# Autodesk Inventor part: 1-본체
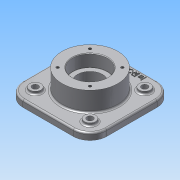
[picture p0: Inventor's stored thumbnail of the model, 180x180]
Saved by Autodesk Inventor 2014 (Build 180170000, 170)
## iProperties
Created: 2015-09
Part Number: 1-본체
Material: 알루미늄 6061
Document SubType Name: Modeling
Designer: study
Density: 2.71 g/cm^3
Appearance: 알루미늄 - 평지
Mass: 1464.68 g
Surface Area: 800.934 cm^2
Volume: 540.471 cm^3
Author: study
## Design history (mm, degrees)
sketch "스케치1"
  geometry: L1 (75, -75)-(-75, -75); L2 (-75, -75)-(-75, 75); L3 (-75, 75)-(75, 75); L4 (75, 75)-(75, -75); 3 further points
  constraints: 8 end point, 1 coincident, 1 midpoint, 1 vertical alignment, 9 other
  dimensions: "d0" = 150 distance of L2.end L3.end
extrude "돌출1" new body sketch "스케치1" distance "d1" = 12; taper "d2" = 0 deg
fillet "모깎기1" dims "d3" = 30
sketch "스케치2"
  geometry: C1 r 50 at (0, 0); 1 further point
  constraints: 1 centre point, 1 coincident
  dimensions: "d4" = 100 diameter of C1
extrude "돌출2" join sketch "스케치2" distance "d5" = 23; taper "d6" = 0 deg
node "작업 평면1"
sketch "스케치3"
  geometry: C1 r 50 at (0, 0); 1 further point
  constraints: 1 centre point, 1 coincident
  dimensions: "d8" = 100 diameter of C1
extrude "돌출3" join sketch "스케치3" stored distance "d9" = 23; taper "d10" = 0 deg
hole "구멍1" diameter "d13" = 45; stored, may be unused: countersink angle "d17" = 90 deg, drill point angle "d19" = 0 deg; dims "d11" = 10, "d12" = 10, "d14" = 6, "d15" = 62, "d16" = 22, "d18" = 8
hole "구멍2" diameter "d22" = 45; stored, may be unused: countersink angle "d26" = 90 deg, drill point angle "d28" = 0 deg; dims "d20" = 10, "d21" = 10, "d23" = 6, "d24" = 62, "d25" = 22, "d27" = 8
node "작업 평면2"
sketch "스케치5"
  geometry: L1 (49, -49)-(-49, -49); L2 (-49, -49)-(-49, 49); L3 (-49, 49)-(49, 49); L4 (49, 49)-(49, -49); C1 r 10 at (-49, 49); C2 r 10 at (49, 49); C3 r 10 at (49, -49); C4 r 10 at (-49, -49); 3 further points
  constraints: 8 end point, 5 coincident, 4 centre point, 3 equal radius, 1 midpoint, 1 vertical alignment, 9 other
  dimensions: "d31" = 98 distance of L2.end L3.end; "d32" = 20 diameter of C1
extrude "돌출4" join sketch "스케치5" stored distance "d33" = 23; taper "d34" = 0 deg
sketch "스케치6"
  geometry: C1 r 10 at (0, 0) reference; C2 r 10 at (0, 98) reference; C3 r 10 at (-98, 98) reference; C4 r 10 at (-98, 0) reference; 5 further points
  constraints: 4 coincident
hole "구멍3" sketch "스케치6" at (0, 98), (0, 0), (-98, 0), (-98, 98) diameter "d35" = 11; stored, may be unused: countersink angle "d39" = 90 deg, drill point angle "d41" = 0 deg; dims "d36" = 6, "d37" = 62, "d38" = 22, "d40" = 8
sketch "스케치7"
  geometry: L1 (28.991, -28.991)-(-28.991, -28.991); L2 (-28.991, -28.991)-(-28.991, 28.991); L3 (-28.991, 28.991)-(28.991, 28.991); L4 (28.991, 28.991)-(28.991, -28.991); C1 r 50 at (0, 0) reference; 6 further points
  constraints: 8 end point, 5 coincident, 1 midpoint, 1 vertical alignment, 9 other
  dimensions: "d42" = 82 distance of L1.start L2.end
hole "구멍4" sketch "스케치7" at (28.991, 28.991), (28.991, -28.991), (-28.991, -28.991), (-28.991, 28.991) diameter "d43" = 4.917; stored, may be unused: countersink angle "d47" = 90 deg, drill point angle "d49" = 118 deg; dims "d44" = 10, "d45" = 62, "d46" = 22, "d48" = 13
node "작업 평면3"
sketch "스케치8"
  geometry: C1 r 50 at (0, 0) reference; 1 further point
  constraints: 1 vertical alignment, 1 other
  dimensions: "d50" = 65 distance of C1.centre point (0, 65)
feature "엠보싱1" sketch "스케치8" dims "d0" = 150, "d51" = 1, "d52" = 0
fillet "모깎기2" dims "d53" = 0.3, "d54" = 3
chamfer "모따기1" distance "d55" = 1; stored, may be unused: second distance "d56" = 2, angle "d57" = 45 deg
node "솔리드1"
mirror "대칭1"
other parameters: "d30" = 5
